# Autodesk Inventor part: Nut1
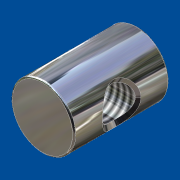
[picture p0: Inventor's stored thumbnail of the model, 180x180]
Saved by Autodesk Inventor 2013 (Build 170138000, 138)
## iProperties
Shininess: 100.0
Length Units: 11269
Angle Units: 11279
Time Units: 11290
Mass Units: 11283
Length Display Precision: 3
Angle Display Precision: 2
Created: 2001-04
Part Number: Nut1
Material: Standard
Document SubType Name: Modellieren
Designer: dl
Density: 1 g/cm^3
Density: 0.0
Volumn: 0.0
Area: 0.0
PropertySet Name: Model Information
Control State: 0
Master: False
Checked Out: False
Author: dl
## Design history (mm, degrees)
body "Solid1"
sketch "Sketch1"
  geometry: C1 r 4 at (0, 0)
  constraints: 1 centre point
  dimensions: "d0" = 8 diameter of C1
extrude "Extrusion1" new body sketch "Sketch1" distance "d1" = 12; taper "d2" = 0 deg
workaxis "Work Axis1"
workplane "Work Plane1"
sketch "Sketch2"
  geometry: L1 (-4, 0)-(4, 0) reference; L2 (4.044, 13.465)-(0, 12); L3 (-4, 12)-(4, 12) reference; 1 further point
  constraints: 2 end point, 1 midpoint
  dimensions: "d4" = 6 distance from line of L1 point (0, 6); "d5" = 0 horizontal distance of L2.end point (0, 6)
hole "Hole1" sketch "Sketch2" diameter "d6" = 4.134; stored, may be unused: countersink angle "d10" = 60 deg, drill point angle "d12" = 118 deg; dims "d7" = 6, "d8" = 4, "d9" = 2, "d11" = 8
chamfer "Chamfer1" distance "d13" = 0.2; stored, may be unused: second distance "d14" = 0.2, angle "d16" = 45 deg
fillet "Fillet1" dims "d15" = 0.2
other parameters: "d3" = 4
